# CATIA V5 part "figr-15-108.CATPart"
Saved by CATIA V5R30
Part number: Part1
Bounding box of the stored display mesh (mm): x -60.955 to 60.955, y -33.748 to 33.748, z 0 to 6.052
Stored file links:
  D:\PROJECTS\CATIA V56R 2020\Resources\Parts File\c15_catia_v5_6r2020_prt\figr-15-108.CATPart
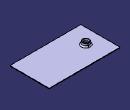
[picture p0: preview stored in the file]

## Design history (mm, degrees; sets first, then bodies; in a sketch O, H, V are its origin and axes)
SheetMetalParameters1: Thickness 1, BendRadius 5, KFactor 0.5 {= log(min(100,max(20*SheetMetalParameters1.BendRadius,SheetMetalParameters1.Thickness)/SheetMetalParameters1.Thickness))/log(100)/2}, ReliefRadialLength 1, ReliefAxialLength 2, MinimumBendRadius 0
Body1 (main body)
  Sketch1 on xy-plane, origin (0, 0, 0), H (1, 0, 0), V (0, 1, 0)
    line L1 (60.9549, 33.7477) -> (60.9549, -33.7477)
    line L2 (60.9549, -33.7477) -> (-60.9549, -33.7477)
    line L3 (-60.9549, -33.7477) -> (-60.9549, 33.7477)
    line L4 (-60.9549, 33.7477) -> (60.9549, 33.7477)
    vertical: L1 V, L3 V
    horizontal: L2 H, L4 H
    equidistance: L1 L3 O, L2 L4 O
  Wall1: Thickness 1, Profile Sketch1
  Sketch2 on face of Wall1, origin (0, 0, 1), H (1, 0, 0), V (0, 1, 0)
    point P1 (-35.8601, 0)
    coincidence: P1 H
  Sketch3 on face of Wall1, origin (-35.8601, 0, 1), H (1, 0, 0), V (0, 1, 0)
    point P1 (0, 0)
    reference projected point E1 (0, 0) from Sketch2.P1
    coincidence: E1 P1
  d_Stamp1: KFacteur 0.5 {= SheetMetalParameters1.KFactor}, Stamp_FilletRadius 2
